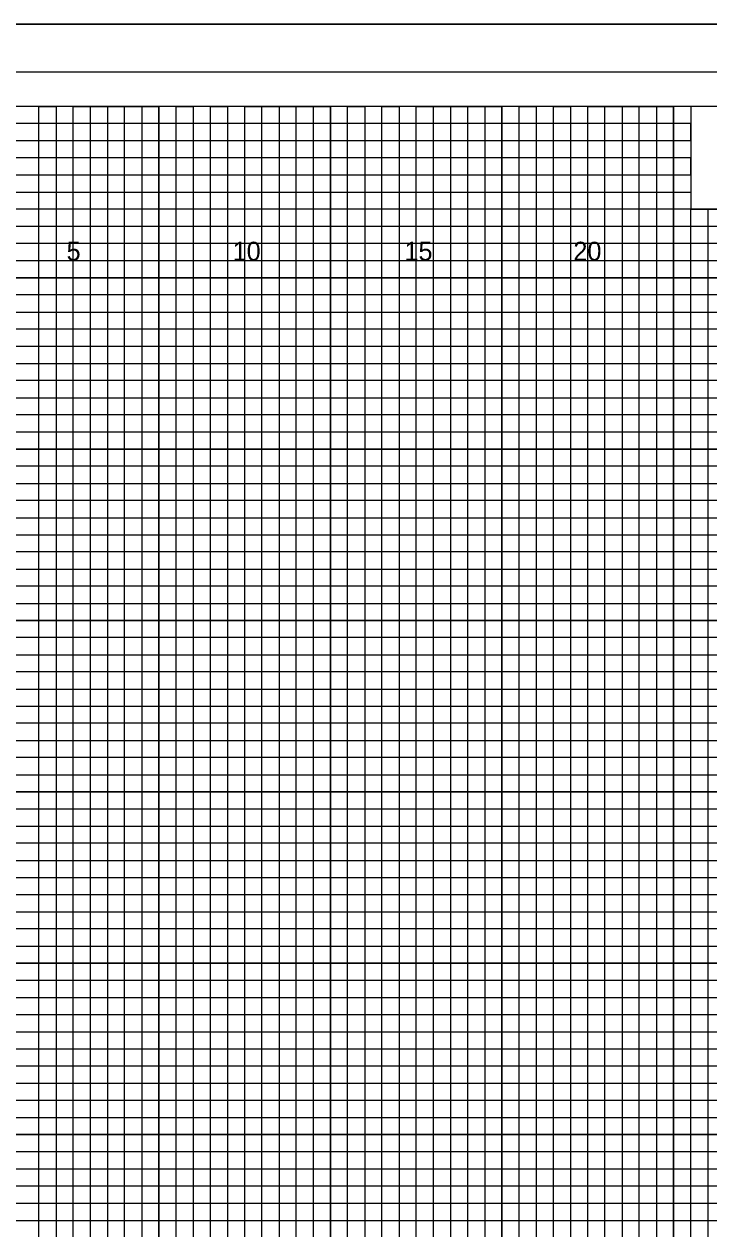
# Model space of a CAD drawing. Extents: x -4 to 103, y -2 to 138.
# Drawn here: x 54.82 to 74.78, y 32.25 to 67.4 of the extents above; entities that cross this region are included whole.
import ezdxf

# ---------------------------------------------------------------- set-up
doc = ezdxf.new("R2010")
doc.units = 0
for name, color, linetype in [('Old_Level_10', 7, 'Continuous'), ('Old_Level_16', 7, 'Continuous'), ('Old_Level_3', 7, 'Continuous'), ('Old_Level_5', 7, 'Continuous'), ('Old_Level_8', 7, 'Continuous'), ('Prop Dimension', 7, 'Continuous'), ('Prop XS SE Text', 7, 'Continuous'), ('Prop XSC Text', 7, 'Continuous')]:
    doc.layers.add(name, color=color, linetype=linetype)

msp = doc.modelspace()

# ---------------------------------------------------------------- linework, layer by layer
at = {"layer": 'Old_Level_10'}
for p, q in [((56.25, 0), (56.25, 65)), ((58.75, 0), (58.75, 65)), ((61.25, 0), (61.25, 65)), ((63.75, 0), (63.75, 65)), ((66.25, 0), (66.25, 65)), ((68.75, 0), (68.75, 65)), ((71.25, 0), (71.25, 65)), ((73.75, 0), (73.75, 65)), ((0, 62.5), (74.25, 62.5)), ((0, 60), (102.5, 60)), ((0, 57.5), (102.5, 57.5)), ((0, 55), (102.5, 55)), ((0, 52.5), (102.5, 52.5)), ((0, 50), (102.5, 50)), ((0, 47.5), (102.5, 47.5)), ((0, 45), (102.5, 45)), ((0, 42.5), (102.5, 42.5)), ((0, 40), (102.5, 40)), ((0, 37.5), (102.5, 37.5)), ((0, 35), (102.5, 35)), ((0, 32.5), (102.5, 32.5))]:
    msp.add_line(p, q, dxfattribs=at)
at = {"layer": 'Old_Level_3'}
msp.add_line((-3.5, 67.4), (103.4, 67.4), dxfattribs=at)
at = {"layer": 'Old_Level_5'}
msp.add_lwpolyline([(103.4, 67.4), (-3.5, 67.4), (-3.5, -2.425), (103.4, -2.425)], close=True, dxfattribs=at)
at = {"layer": 'Old_Level_8'}
for points in [[(56.25, 0), (56.25, 65), (58.75, 65), (58.75, 0)], [(61.25, 0), (61.25, 65), (63.75, 65), (63.75, 0)], [(66.25, 0), (66.25, 65), (68.75, 65), (68.75, 0)], [(71.25, 0), (71.25, 65), (73.75, 65), (73.75, 0)], [(0, 62.5), (74.25, 62.5)], [(0, 57.5), (102.5, 57.5), (102.5, 60), (0, 60)], [(0, 52.5), (102.5, 52.5), (102.5, 55), (0, 55)], [(0, 47.5), (102.5, 47.5), (102.5, 50), (0, 50)], [(0, 42.5), (102.5, 42.5), (102.5, 45), (0, 45)], [(0, 37.5), (102.5, 37.5), (102.5, 40), (0, 40)], [(0, 32.5), (102.5, 32.5), (102.5, 35), (0, 35)]]:
    msp.add_lwpolyline(points, dxfattribs=at)
at = {"layer": 'Prop Dimension'}
for points in [[(55.25, 0), (55.25, 65), (55.75, 65), (55.75, 0)], [(56.75, 0), (56.75, 65), (57.25, 65), (57.25, 0)], [(57.75, 0), (57.75, 65), (58.25, 65), (58.25, 0)], [(59.25, 0), (59.25, 65), (59.75, 65), (59.75, 0)], [(60.25, 0), (60.25, 65), (60.75, 65), (60.75, 0)], [(61.75, 0), (61.75, 65), (62.25, 65), (62.25, 0)], [(62.75, 0), (62.75, 65), (63.25, 65), (63.25, 0)], [(64.25, 0), (64.25, 65), (64.75, 65), (64.75, 0)], [(65.25, 0), (65.25, 65), (65.75, 65), (65.75, 0)], [(66.75, 0), (66.75, 65), (67.25, 65), (67.25, 0)], [(67.75, 0), (67.75, 65), (68.25, 65), (68.25, 0)], [(69.25, 0), (69.25, 65)], [(69.25, 65), (69.75, 65), (69.75, 0)], [(70.25, 0), (70.25, 65), (70.75, 65), (70.75, 0)], [(71.75, 0), (71.75, 65), (72.25, 65), (72.25, 0)], [(72.75, 0), (72.75, 65), (73.25, 65), (73.25, 0)], [(0, 62), (0, 63), (74.25, 63), (74.25, 63.5), (0, 63.5), (0, 64), (74.25, 64), (74.25, 64.5), (0, 64.5)], [(0, 61.5), (102.5, 61.5), (102.5, 62), (0, 62)], [(74.25, 0), (74.25, 62), (74.75, 62), (74.75, 0)], [(0, 60.5), (102.5, 60.5), (102.5, 61), (0, 61)], [(0, 59), (102.5, 59), (102.5, 59.5), (0, 59.5)], [(0, 58), (102.5, 58), (102.5, 58.5), (0, 58.5)], [(0, 56.5), (102.5, 56.5), (102.5, 57), (0, 57)], [(0, 55.5), (102.5, 55.5), (102.5, 56), (0, 56)], [(0, 54), (102.5, 54), (102.5, 54.5), (0, 54.5)], [(0, 53), (102.5, 53), (102.5, 53.5), (0, 53.5)], [(0, 51.5), (102.5, 51.5), (102.5, 52), (0, 52)], [(0, 50.5), (102.5, 50.5), (102.5, 51), (0, 51)], [(0, 49), (102.5, 49), (102.5, 49.5), (0, 49.5)], [(0, 48), (102.5, 48), (102.5, 48.5), (0, 48.5)], [(0, 46.5), (102.5, 46.5), (102.5, 47), (0, 47)], [(0, 45.5), (102.5, 45.5), (102.5, 46), (0, 46)], [(0, 44), (102.5, 44), (102.5, 44.5), (0, 44.5)], [(0, 43), (102.5, 43), (102.5, 43.5), (0, 43.5)], [(0, 41.5), (102.5, 41.5), (102.5, 42), (0, 42)], [(0, 40.5), (102.5, 40.5), (102.5, 41), (0, 41)], [(0, 39), (102.5, 39), (102.5, 39.5), (0, 39.5)], [(0, 38), (102.5, 38), (102.5, 38.5), (0, 38.5)], [(0, 36.5), (102.5, 36.5), (102.5, 37), (0, 37)], [(0, 35.5), (102.5, 35.5), (102.5, 36), (0, 36)], [(0, 34), (102.5, 34), (102.5, 34.5), (0, 34.5)], [(0, 33), (102.5, 33), (102.5, 33.5), (0, 33.5)]]:
    msp.add_lwpolyline(points, dxfattribs=at)
at = {"layer": 'Prop XS SE Text'}
msp.add_lwpolyline([(103, 66), (-2.8, 66), (-2.8, -1), (103, -1)], close=True, dxfattribs=at)
at = {"layer": 'Prop XSC Text'}
for points in [[(102.5, 65), (0, 65), (0, 0), (102.5, 0)], [(83.75, 65), (74.25, 65), (74.25, 62), (83.75, 62)]]:
    msp.add_lwpolyline(points, close=True, dxfattribs=at)

# ---------------------------------------------------------------- texts
at = {"layer": 'Old_Level_16'}
for s, p in [('5', (56.057, 60.5)), ('10', (60.897, 60.5)), ('15', (65.906, 60.5)), ('20', (70.831, 60.5))]:
    msp.add_text(s, height=0.55, dxfattribs=at).set_placement(p)

doc.saveas('drawing.dxf')
